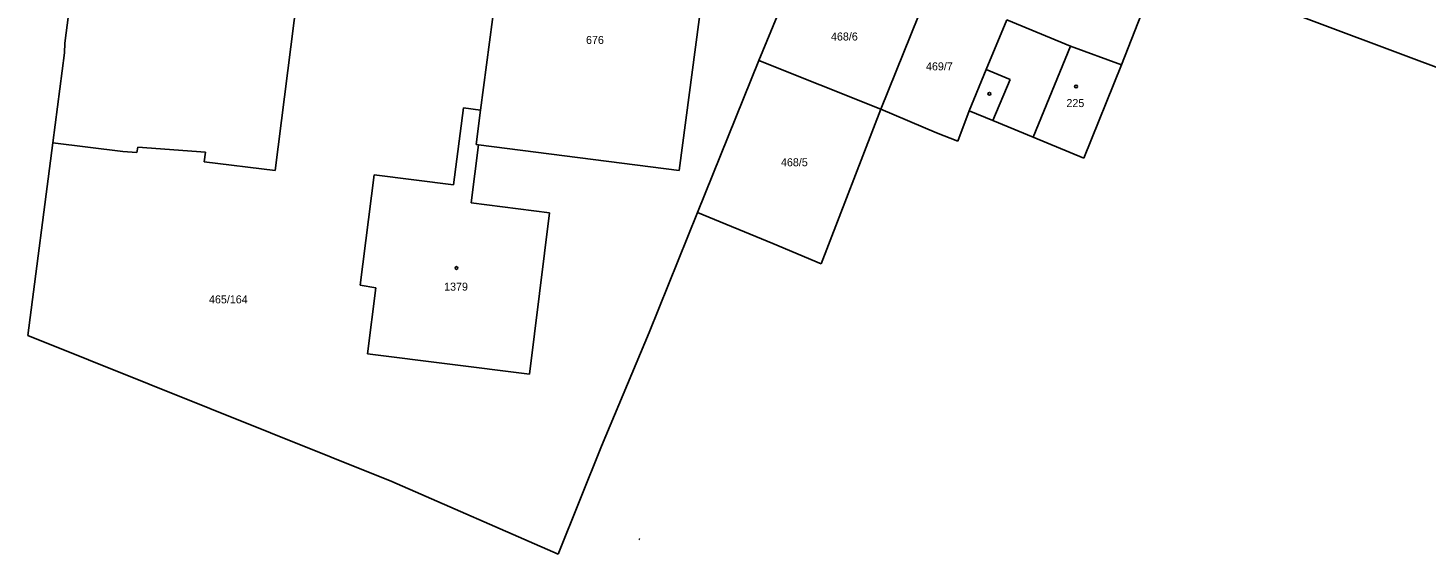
# Model space of a CAD drawing. Extents: x -643859 to -643594, y -1190913 to -1190609.
# Drawn here: x -643859.2 to -643684.5, y -1190912.8 to -1190847 of the extents above; entities that cross this region are included whole.
import ezdxf

# ---------------------------------------------------------------- set-up
doc = ezdxf.new("R2010")
doc.units = 0
for name, color, linetype in [('Hranice parcel', 7, 'Continuous'), ('Vrstva 1', 7, 'Continuous'), ('Vrstva 11', 7, 'Continuous'), ('Vrstva 38', 7, 'Continuous'), ('Vrstva 63', 7, 'Continuous')]:
    doc.layers.add(name, color=color, linetype=linetype)

msp = doc.modelspace()

# ---------------------------------------------------------------- linework, layer by layer
at = {"layer": 'Hranice parcel'}
for p, q in [((-643854.57, -1190848.9), (-643851.42, -1190824.42)), ((-643823.58, -1190827.65), (-643828.28, -1190864.83)), ((-643802.61, -1190857.27), (-643799.11, -1190830.31)), ((-643773.67, -1190833.43), (-643777.78, -1190864.8)), ((-643767.84, -1190851.05), (-643761.82, -1190836.51)), ((-643717.52, -1190838.75), (-643722.51, -1190851.6)), ((-643752.62, -1190857.15), (-643746.6, -1190842.29)), ((-643704.91, -1190843.78), (-643659.76, -1190860.7)), ((-643736.85, -1190845.99), (-643739.43, -1190852.2)), ((-643728.92, -1190849.25), (-643736.85, -1190845.99)), ((-643856.05, -1190861.35), (-643854.62, -1190850.08)), ((-643854.62, -1190850.08), (-643854.57, -1190848.9)), ((-643722.51, -1190851.6), (-643728.92, -1190849.25)), ((-643775.5, -1190870.08), (-643767.84, -1190851.05)), ((-643767.84, -1190851.05), (-643752.62, -1190857.15)), ((-643727.25, -1190863.25), (-643722.51, -1190851.6)), ((-643739.43, -1190852.2), (-643741.56, -1190857.34)), ((-643806, -1190866.62), (-643804.74, -1190856.99)), ((-643802.61, -1190857.27), (-643804.74, -1190856.99)), ((-643803.17, -1190861.58), (-643802.61, -1190857.27)), ((-643752.62, -1190857.15), (-643760.07, -1190876.46)), ((-643745.63, -1190860.09), (-643752.62, -1190857.15)), ((-643741.56, -1190857.34), (-643743, -1190861.16)), ((-643738.59, -1190858.56), (-643741.56, -1190857.34)), ((-643736.71, -1190859.34), (-643738.59, -1190858.56)), ((-643745.63, -1190860.09), (-643743, -1190861.16)), ((-643733.56, -1190860.64), (-643736.71, -1190859.34)), ((-643727.25, -1190863.25), (-643733.56, -1190860.64)), ((-643856.05, -1190861.35), (-643859.17, -1190885.42)), ((-643856.05, -1190861.35), (-643847.33, -1190862.44)), ((-643847.33, -1190862.44), (-643845.56, -1190862.56)), ((-643845.56, -1190862.56), (-643845.44, -1190861.9)), ((-643837, -1190862.53), (-643845.44, -1190861.9)), ((-643837, -1190862.53), (-643837.15, -1190863.72)), ((-643803.79, -1190868.84), (-643802.88, -1190861.62)), ((-643802.88, -1190861.62), (-643803.17, -1190861.58)), ((-643777.78, -1190864.8), (-643802.88, -1190861.62)), ((-643828.28, -1190864.83), (-643837.15, -1190863.72)), ((-643815.9, -1190865.37), (-643817.66, -1190879.13)), ((-643806, -1190866.62), (-643815.9, -1190865.37)), ((-643794, -1190870.09), (-643803.79, -1190868.84)), ((-643796.52, -1190890.27), (-643794, -1190870.09)), ((-643781.57, -1190885.08), (-643775.5, -1190870.08)), ((-643775.5, -1190870.08), (-643766.11, -1190873.94)), ((-643766.11, -1190873.94), (-643760.07, -1190876.46)), ((-643817.66, -1190879.13), (-643815.72, -1190879.46)), ((-643815.72, -1190879.46), (-643816.73, -1190887.75)), ((-643787.49, -1190899.29), (-643781.57, -1190885.08)), ((-643859.17, -1190885.42), (-643813.69, -1190903.69)), ((-643816.73, -1190887.75), (-643796.52, -1190890.27)), ((-643792.93, -1190912.76), (-643787.49, -1190899.29)), ((-643813.69, -1190903.69), (-643792.93, -1190912.76)), ((-643782.71, -1190910.92), (-643782.86, -1190910.87))]:
    msp.add_line(p, q, dxfattribs=at)
at = {"layer": 'Vrstva 1'}
for p, q in [((-643728.92, -1190849.25), (-643733.56, -1190860.64)), ((-643739.43, -1190852.2), (-643736.46, -1190853.43)), ((-643738.59, -1190858.56), (-643736.46, -1190853.43))]:
    msp.add_line(p, q, dxfattribs=at)
at = {"layer": 'Vrstva 11'}
for centre in [(-643728.21, -1190854.32), (-643805.63, -1190877)]:
    msp.add_circle(centre, 0.175, dxfattribs=at)
at = {"layer": 'Vrstva 38'}
msp.add_circle((-643739.04, -1190855.22), 0.175, dxfattribs=at)

# ---------------------------------------------------------------- texts
at = {"layer": 'Vrstva 63'}
for s, p in [('676', (-643789.44, -1190848.99)), ('468/6', (-643758.83, -1190848.56)), ('469/7', (-643746.96, -1190852.29)), ('225', (-643729.41, -1190856.88)), ('468/5', (-643765.08, -1190864.28)), ('1379', (-643807.17, -1190879.83)), ('465/164', (-643836.55, -1190881.42))]:
    msp.add_text(s, height=1, dxfattribs=at).set_placement(p)

doc.saveas('drawing.dxf')
